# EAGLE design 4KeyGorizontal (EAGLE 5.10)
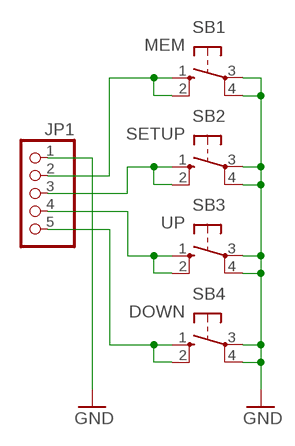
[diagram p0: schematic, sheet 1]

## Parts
JP1  PINHD-1X5  [1X05]
SB1  MEM  40-XX  [B3F-40XX]
SB2  SETUP  40-XX  [B3F-40XX]
SB3  UP  40-XX  [B3F-40XX]
SB4  DOWN  40-XX  [B3F-40XX]

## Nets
GND: JP1.1 SB1.3(P) SB1.4(P1) SB2.3(P) SB2.4(P1) SB3.3(P) SB3.4(P1) SB4.3(P) SB4.4(P1)
N$13: JP1.2 SB1.1(S) SB1.2(S1)
N$14: JP1.3 SB2.1(S) SB2.2(S1)
N$15: JP1.4 SB3.1(S) SB3.2(S1)
N$16: JP1.5 SB4.1(S) SB4.2(S1)

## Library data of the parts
JP1 = pinhead:PINHD-1X5: PIN HEADER
SB1-SB4 = switch-omron:40-XX: OMRON SWITCH

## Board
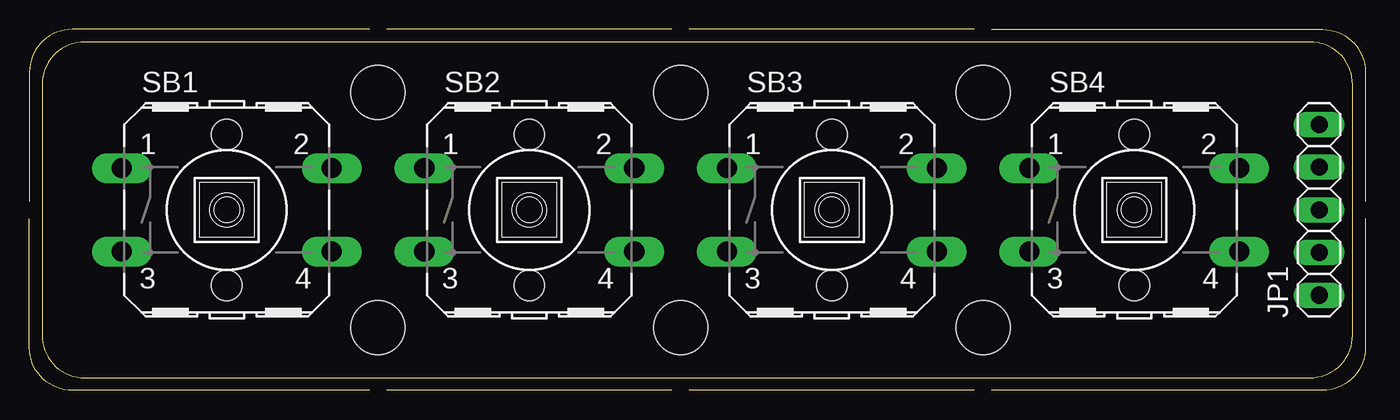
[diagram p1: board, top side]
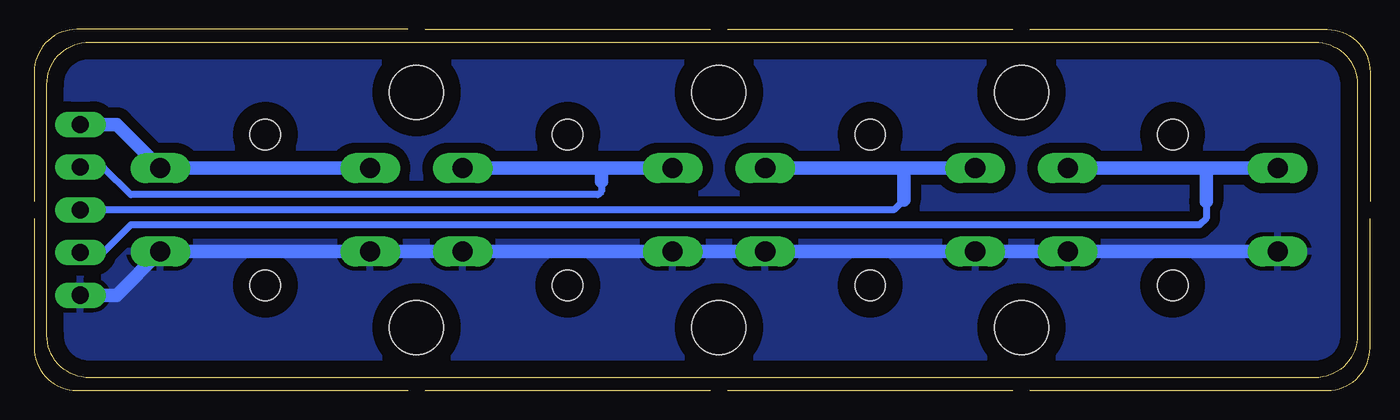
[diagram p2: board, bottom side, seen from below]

Size 78 x 20 mm. Coordinates in mm from the lower left corner, seen from the top.
Outline: 2.54,20 arc90 0,17.46 0,2.54 arc90 2.54,0 75.46,0 arc90 78,2.54 78,17.46 arc90 75.46,20 2.54,20
Copper layers (1*16): Top 0.035mm / dielectric 1.5mm / Bottom 0.035mm
Design rules "default": minimum track width 10mil, minimum drill 24mil, track to track 8mil, track to pad 8mil, pad to pad 8mil, via to via 8mil, smd to smd 8mil, copper to edge 40mil, drill to drill 8mil, minimum pad ring 10mil, minimum via ring 8mil, stop-mask expansion 4mil, vias tented up to drill 0mil, thermal gap 10mil
Holes 3.2 mm at 20,17 20,3 38,17 38,3 56,17 56,3 -5,17 -5,3 83,3 83,17
Holes 3.1 mm at 83,10 -5,10
Milling: 24 lines

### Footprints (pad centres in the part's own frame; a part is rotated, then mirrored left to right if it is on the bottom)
1X05 = drill 1.016 long: 1 -5.08,0; 2 -2.54,0; 3 0,0; 4 2.54,0; 5 5.08,0
B3F-40XX = drill 1.194 long: 1 -6.248,2.489; 2 6.248,2.489; 3 -6.248,-2.489; 4 6.248,-2.489 | hole 1.803: 0,-4.496; 0,4.496

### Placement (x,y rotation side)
JP1  76,10 90 top
SB1  11,10 0 top
SB2  29,10 0 top
SB3  47,10 0 top
SB4  65,10 0 top

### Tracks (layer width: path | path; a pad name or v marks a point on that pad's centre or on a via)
GND
  Bottom 0.813: SB1.3 SB1.4 SB2.3 SB2.4 SB3.3 SB3.4 SB4.3 SB4.4 73.84,4.92 JP1.1
  pour Bottom (isolate 0.61): 2.54,20 arc90 0,17.46 0,2.54 arc90 2.54,0 75.46,0 arc90 78,2.54 78,17.46 arc90 75.46,20
N$13
  Bottom 0.406: 9,10.5 9,9.5 9.4,9.1 73,9.1 74.6,7.5 75.96,7.5 JP1.2
  Bottom 0.813: SB1.1 9,12.49 | 9,12.49 SB1.2 | 9,12.49 9,10.5
N$14
  Bottom 0.406: JP1.3 27.6,10 27,10.6
  Bottom 0.813: SB2.1 27,12.49 | 27,12.49 SB2.2 | 27,12.49 27,10.6
N$15
  Bottom 0.406: 45,11.7 45,11.1 45.2,10.9 73,10.9 74.6,12.5 75.96,12.5 JP1.4
  Bottom 0.813: SB3.1 45,12.49 | 45,12.49 46.59,12.49 46.6,12.5 51.24,12.5 SB3.2 | 45,12.49 45,11.7
N$16
  Bottom 0.813: SB4.1 SB4.2 73.84,15.08 JP1.5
